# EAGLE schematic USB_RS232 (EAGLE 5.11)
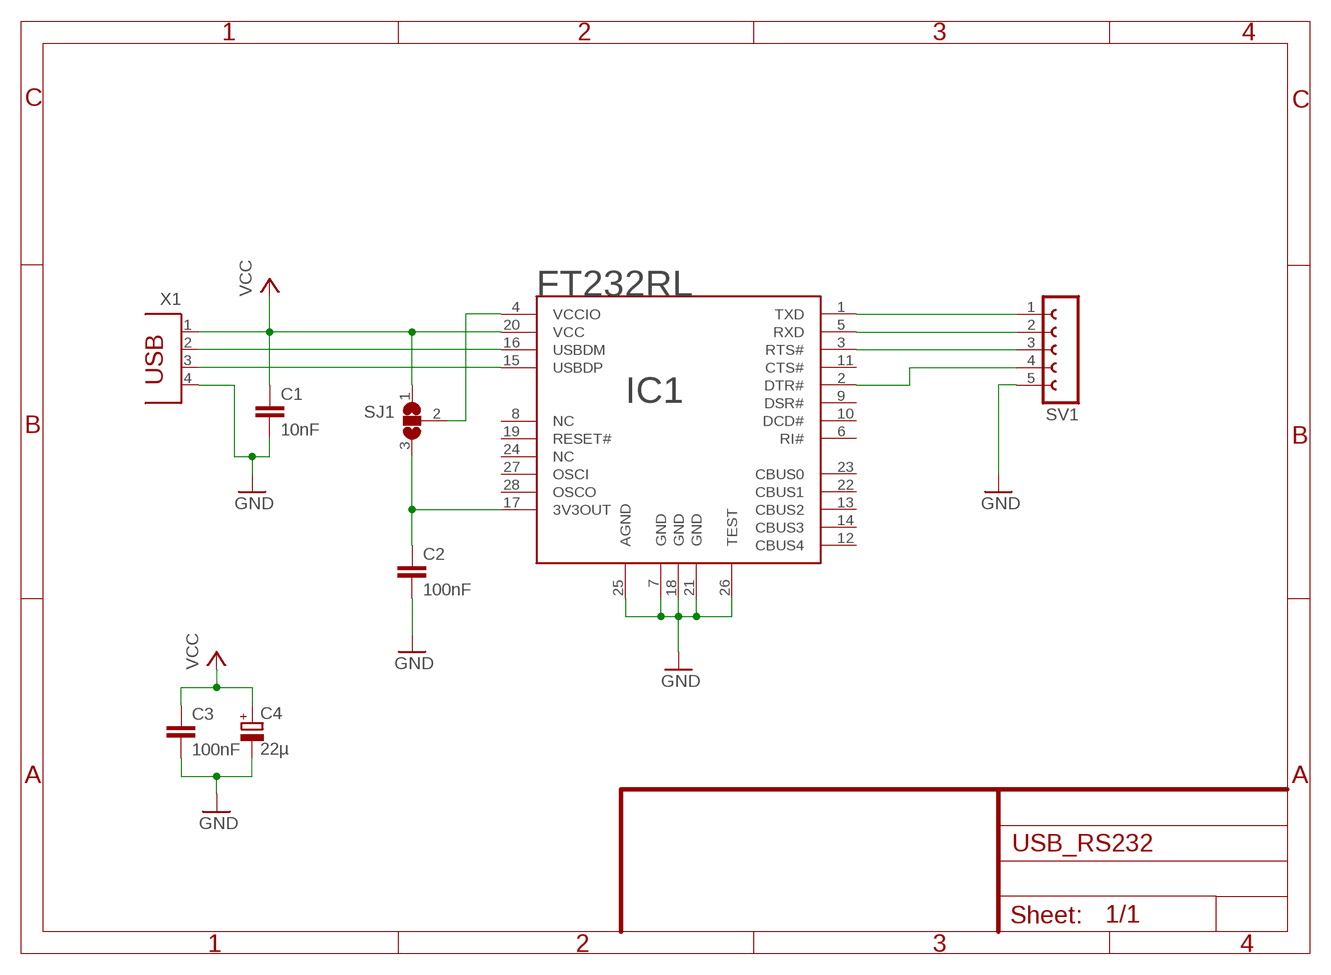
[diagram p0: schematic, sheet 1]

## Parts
C1  10nF  C-EUC0805  [C0805]
C2  100nF  C-EUC0805  [C0805]
C3  100nF  C-EUC0805  [C0805]
C4  22µ  CPOL-EU085CS-1AR  [085CS_1AR]
IC1  FT232RL  [SSOP28]
SJ1  SJ2W  [SJ_2]
SV1  FE05-1  [FE05-1]
X1  PN61729  [PN61729]

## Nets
DTR: IC1.2(DTR#) SV1.4
GND: C1.2 C2.2 C3.2 C4.- IC1.7(GND) IC1.18(GND) IC1.21(GND) IC1.25(AGND) IC1.26(TEST) SV1.5 X1.4
N$1: IC1.16(USBDM) X1.2
N$2: IC1.15(USBDP) X1.3
N$5: C2.1 IC1.17(3V3OUT) SJ1.3
N$9: IC1.4(VCCIO) SJ1.2
RTS: IC1.3(RTS#) SV1.3
RXD: IC1.5(RXD) SV1.2
TXD: IC1.1(TXD) SV1.1
VCC: C1.1 C3.1 C4.+ IC1.20(VCC) SJ1.1 X1.1
Unconnected: IC1.6(RI#) IC1.8(NC) IC1.9(DSR#) IC1.10(DCD#) IC1.11(CTS#) IC1.12(CBUS4) IC1.13(CBUS2) IC1.14(CBUS3) IC1.19(RESET#) IC1.22(CBUS1) IC1.23(CBUS0) IC1.24(NC) IC1.27(OSCI) IC1.28(OSCO)

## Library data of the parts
C1-C3 = rcl:C-EU: CAPACITOR, European symbol
C4 = rcl:CPOL-EU: POLARIZED CAPACITOR, European symbol
IC1 = FTDI:FT232RL
SJ1 = jumper:SJ2W: SMD solder JUMPER
SV1 = con-lsta:FE05-1: FEMALE HEADER
X1 = con-berg:PN61729: BERG USB connector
